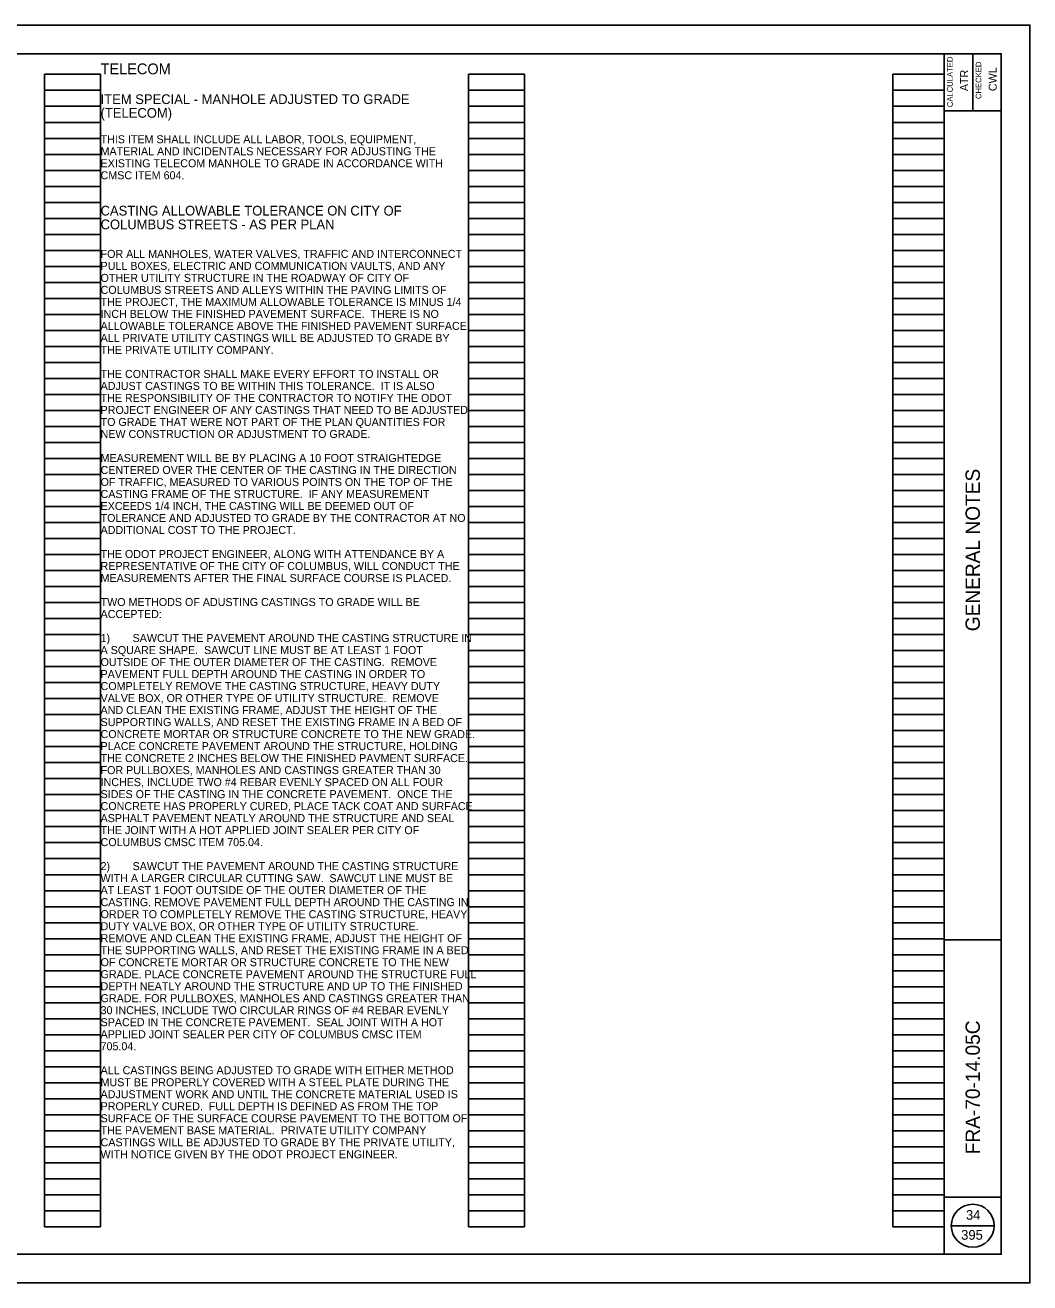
# Model space of a CAD drawing. Extents: x 0 to 34, y 0 to 22.
# Drawn here: x 16.42 to 34, y 0 to 22 of the extents above; entities that cross this region are included whole.
import ezdxf

# ---------------------------------------------------------------- set-up
doc = ezdxf.new("R2010")
doc.units = 0
for name, color, linetype in [('SC_Scratch1', 7, 'Continuous'), ('SH_Border', 7, 'Continuous'), ('SH_Cut_Line', 7, 'Continuous'), ('SH_Data', 7, 'Continuous'), ('SH_Text', 7, 'Continuous'), ('TX_P_1', 7, 'Continuous'), ('TX_P_Misc', 7, 'Continuous')]:
    doc.layers.add(name, color=color, linetype=linetype)

msp = doc.modelspace()

# ---------------------------------------------------------------- linework, layer by layer
at = {"layer": 'SC_Scratch1'}
for p, q in [((16.76, 0.98), (16.76, 21.14)), ((16.76, 21.14), (17.74, 21.14)), ((17.74, 0.98), (17.74, 21.14)), ((24.18, 0.98), (24.18, 21.14)), ((24.18, 21.14), (25.16, 21.14)), ((25.16, 0.98), (25.16, 21.14)), ((31.6, 0.98), (31.6, 21.14)), ((31.6, 21.14), (32.5, 21.14)), ((32.5, 0.98), (32.5, 21.14)), ((16.76, 20.86), (17.74, 20.86)), ((24.18, 20.86), (25.16, 20.86)), ((31.6, 20.86), (32.5, 20.86)), ((16.76, 20.58), (17.74, 20.58)), ((24.18, 20.58), (25.16, 20.58)), ((31.6, 20.58), (32.5, 20.58)), ((16.76, 20.3), (17.74, 20.3)), ((24.18, 20.3), (25.16, 20.3)), ((31.6, 20.3), (32.5, 20.3)), ((16.76, 20.02), (17.74, 20.02)), ((24.18, 20.02), (25.16, 20.02)), ((31.6, 20.02), (32.5, 20.02)), ((16.76, 19.74), (17.74, 19.74)), ((24.18, 19.74), (25.16, 19.74)), ((31.6, 19.74), (32.5, 19.74)), ((16.76, 19.46), (17.74, 19.46)), ((24.18, 19.46), (25.16, 19.46)), ((31.6, 19.46), (32.5, 19.46)), ((16.76, 19.18), (17.74, 19.18)), ((24.18, 19.18), (25.16, 19.18)), ((31.6, 19.18), (32.5, 19.18)), ((16.76, 18.9), (17.74, 18.9)), ((24.18, 18.9), (25.16, 18.9)), ((31.6, 18.9), (32.5, 18.9)), ((16.76, 18.62), (17.74, 18.62)), ((24.18, 18.62), (25.16, 18.62)), ((31.6, 18.62), (32.5, 18.62)), ((16.76, 18.34), (17.74, 18.34)), ((24.18, 18.34), (25.16, 18.34)), ((31.6, 18.34), (32.5, 18.34)), ((16.76, 18.06), (17.74, 18.06)), ((24.18, 18.06), (25.16, 18.06)), ((31.6, 18.06), (32.5, 18.06)), ((16.76, 17.78), (17.74, 17.78)), ((24.18, 17.78), (25.16, 17.78)), ((31.6, 17.78), (32.5, 17.78)), ((16.76, 17.5), (17.74, 17.5)), ((24.18, 17.5), (25.16, 17.5)), ((31.6, 17.5), (32.5, 17.5)), ((16.76, 17.22), (17.74, 17.22)), ((24.18, 17.22), (25.16, 17.22)), ((31.6, 17.22), (32.5, 17.22)), ((16.76, 16.94), (17.74, 16.94)), ((24.18, 16.94), (25.16, 16.94)), ((31.6, 16.94), (32.5, 16.94)), ((16.76, 16.66), (17.74, 16.66)), ((24.18, 16.66), (25.16, 16.66)), ((31.6, 16.66), (32.5, 16.66)), ((16.76, 16.38), (17.74, 16.38)), ((24.18, 16.38), (25.16, 16.38)), ((31.6, 16.38), (32.5, 16.38)), ((16.76, 16.1), (17.74, 16.1)), ((24.18, 16.1), (25.16, 16.1)), ((31.6, 16.1), (32.5, 16.1)), ((16.76, 15.82), (17.74, 15.82)), ((24.18, 15.82), (25.16, 15.82)), ((31.6, 15.82), (32.5, 15.82)), ((16.76, 15.54), (17.74, 15.54)), ((24.18, 15.54), (25.16, 15.54)), ((31.6, 15.54), (32.5, 15.54)), ((16.76, 15.26), (17.74, 15.26)), ((24.18, 15.26), (25.16, 15.26)), ((31.6, 15.26), (32.5, 15.26)), ((16.76, 14.98), (17.74, 14.98)), ((24.18, 14.98), (25.16, 14.98)), ((31.6, 14.98), (32.5, 14.98)), ((16.76, 14.7), (17.74, 14.7)), ((24.18, 14.7), (25.16, 14.7)), ((31.6, 14.7), (32.5, 14.7)), ((16.76, 14.42), (17.74, 14.42)), ((24.18, 14.42), (25.16, 14.42)), ((31.6, 14.42), (32.5, 14.42)), ((16.76, 14.14), (17.74, 14.14)), ((24.18, 14.14), (25.16, 14.14)), ((31.6, 14.14), (32.5, 14.14)), ((16.76, 13.86), (17.74, 13.86)), ((24.18, 13.86), (25.16, 13.86)), ((31.6, 13.86), (32.5, 13.86)), ((16.76, 13.58), (17.74, 13.58)), ((24.18, 13.58), (25.16, 13.58)), ((31.6, 13.58), (32.5, 13.58)), ((16.76, 13.3), (17.74, 13.3)), ((24.18, 13.3), (25.16, 13.3)), ((31.6, 13.3), (32.5, 13.3)), ((16.76, 13.02), (17.74, 13.02)), ((24.18, 13.02), (25.16, 13.02)), ((31.6, 13.02), (32.5, 13.02)), ((16.76, 12.74), (17.74, 12.74)), ((24.18, 12.74), (25.16, 12.74)), ((31.6, 12.74), (32.5, 12.74)), ((16.76, 12.46), (17.74, 12.46)), ((24.18, 12.46), (25.16, 12.46)), ((31.6, 12.46), (32.5, 12.46)), ((16.76, 12.18), (17.74, 12.18)), ((24.18, 12.18), (25.16, 12.18)), ((31.6, 12.18), (32.5, 12.18)), ((16.76, 11.9), (17.74, 11.9)), ((24.18, 11.9), (25.16, 11.9)), ((31.6, 11.9), (32.5, 11.9)), ((16.76, 11.62), (17.74, 11.62)), ((24.18, 11.62), (25.16, 11.62)), ((31.6, 11.62), (32.5, 11.62)), ((16.76, 11.34), (17.74, 11.34)), ((24.18, 11.34), (25.16, 11.34)), ((31.6, 11.34), (32.5, 11.34)), ((16.76, 11.06), (17.74, 11.06)), ((24.18, 11.06), (25.16, 11.06)), ((31.6, 11.06), (32.5, 11.06)), ((16.76, 10.78), (17.74, 10.78)), ((24.18, 10.78), (25.16, 10.78)), ((31.6, 10.78), (32.5, 10.78)), ((16.76, 10.5), (17.74, 10.5)), ((24.18, 10.5), (25.16, 10.5)), ((31.6, 10.5), (32.5, 10.5)), ((16.76, 10.22), (17.74, 10.22)), ((24.18, 10.22), (25.16, 10.22)), ((31.6, 10.22), (32.5, 10.22)), ((16.76, 9.94), (17.74, 9.94)), ((24.18, 9.94), (25.16, 9.94)), ((31.6, 9.94), (32.5, 9.94)), ((16.76, 9.66), (17.74, 9.66)), ((24.18, 9.66), (25.16, 9.66)), ((31.6, 9.66), (32.5, 9.66)), ((16.76, 9.38), (17.74, 9.38)), ((24.18, 9.38), (25.16, 9.38)), ((31.6, 9.38), (32.5, 9.38)), ((16.76, 9.1), (17.74, 9.1)), ((24.18, 9.1), (25.16, 9.1)), ((31.6, 9.1), (32.5, 9.1)), ((16.76, 8.82), (17.74, 8.82)), ((24.18, 8.82), (25.16, 8.82)), ((31.6, 8.82), (32.5, 8.82)), ((16.76, 8.54), (17.74, 8.54)), ((24.18, 8.54), (25.16, 8.54)), ((31.6, 8.54), (32.5, 8.54)), ((16.76, 8.26), (17.74, 8.26)), ((24.18, 8.26), (25.16, 8.26)), ((31.6, 8.26), (32.5, 8.26)), ((16.76, 7.98), (17.74, 7.98)), ((24.18, 7.98), (25.16, 7.98)), ((31.6, 7.98), (32.5, 7.98)), ((16.76, 7.7), (17.74, 7.7)), ((24.18, 7.7), (25.16, 7.7)), ((31.6, 7.7), (32.5, 7.7)), ((16.76, 7.42), (17.74, 7.42)), ((24.18, 7.42), (25.16, 7.42)), ((31.6, 7.42), (32.5, 7.42)), ((16.76, 7.14), (17.74, 7.14)), ((24.18, 7.14), (25.16, 7.14)), ((31.6, 7.14), (32.5, 7.14)), ((16.76, 6.86), (17.74, 6.86)), ((24.18, 6.86), (25.16, 6.86)), ((31.6, 6.86), (32.5, 6.86)), ((16.76, 6.58), (17.74, 6.58)), ((24.18, 6.58), (25.16, 6.58)), ((31.6, 6.58), (32.5, 6.58)), ((16.76, 6.3), (17.74, 6.3)), ((24.18, 6.3), (25.16, 6.3)), ((31.6, 6.3), (32.5, 6.3)), ((16.76, 6.02), (17.74, 6.02)), ((24.18, 6.02), (25.16, 6.02)), ((31.6, 6.02), (32.5, 6.02)), ((16.76, 5.74), (17.74, 5.74)), ((24.18, 5.74), (25.16, 5.74)), ((31.6, 5.74), (32.5, 5.74)), ((16.76, 5.46), (17.74, 5.46)), ((24.18, 5.46), (25.16, 5.46)), ((31.6, 5.46), (32.5, 5.46)), ((16.76, 5.18), (17.74, 5.18)), ((24.18, 5.18), (25.16, 5.18)), ((31.6, 5.18), (32.5, 5.18)), ((16.76, 4.9), (17.74, 4.9)), ((24.18, 4.9), (25.16, 4.9)), ((31.6, 4.9), (32.5, 4.9)), ((16.76, 4.62), (17.74, 4.62)), ((24.18, 4.62), (25.16, 4.62)), ((31.6, 4.62), (32.5, 4.62)), ((16.76, 4.34), (17.74, 4.34)), ((24.18, 4.34), (25.16, 4.34)), ((31.6, 4.34), (32.5, 4.34)), ((16.76, 4.06), (17.74, 4.06)), ((24.18, 4.06), (25.16, 4.06)), ((31.6, 4.06), (32.5, 4.06)), ((16.76, 3.78), (17.74, 3.78)), ((24.18, 3.78), (25.16, 3.78)), ((31.6, 3.78), (32.5, 3.78)), ((16.76, 3.5), (17.74, 3.5)), ((24.18, 3.5), (25.16, 3.5)), ((31.6, 3.5), (32.5, 3.5)), ((16.76, 3.22), (17.74, 3.22)), ((24.18, 3.22), (25.16, 3.22)), ((31.6, 3.22), (32.5, 3.22)), ((16.76, 2.94), (17.74, 2.94)), ((24.18, 2.94), (25.16, 2.94)), ((31.6, 2.94), (32.5, 2.94)), ((16.76, 2.66), (17.74, 2.66)), ((24.18, 2.66), (25.16, 2.66)), ((31.6, 2.66), (32.5, 2.66)), ((16.76, 2.38), (17.74, 2.38)), ((24.18, 2.38), (25.16, 2.38)), ((31.6, 2.38), (32.5, 2.38)), ((16.76, 2.1), (17.74, 2.1)), ((24.18, 2.1), (25.16, 2.1)), ((31.6, 2.1), (32.5, 2.1)), ((16.76, 1.82), (17.74, 1.82)), ((24.18, 1.82), (25.16, 1.82)), ((31.6, 1.82), (32.5, 1.82)), ((16.76, 1.54), (17.74, 1.54)), ((24.18, 1.54), (25.16, 1.54)), ((31.6, 1.54), (32.5, 1.54)), ((16.76, 1.26), (17.74, 1.26)), ((24.18, 1.26), (25.16, 1.26)), ((31.6, 1.26), (32.5, 1.26)), ((16.76, 0.98), (17.74, 0.98)), ((24.18, 0.98), (25.16, 0.98)), ((31.6, 0.98), (32.5, 0.98))]:
    msp.add_line(p, q, dxfattribs=at)
at = {"layer": 'SH_Border'}
for p, q in [((32.5, 0.5), (32.5, 21.5)), ((33, 21.5), (33, 20.5)), ((32.5, 20.5), (33.5, 20.5)), ((32.5, 6), (33.5, 6)), ((32.5, 1.5), (33.5, 1.5))]:
    msp.add_line(p, q, dxfattribs=at)
msp.add_lwpolyline([(2, 21.5), (33.5, 21.5), (33.5, 0.5), (2, 0.5)], close=True, dxfattribs=at)
at = {"layer": 'SH_Cut_Line'}
msp.add_lwpolyline([(0, 0), (34, 0), (34, 22), (0, 22)], close=True, dxfattribs=at)
at = {"layer": 'SH_Data'}
msp.add_line((32.625, 1), (33.375, 1), dxfattribs=at)
msp.add_circle((33, 1), 0.375, dxfattribs=at)

# ---------------------------------------------------------------- texts
for s, height, p in [('CALCULATED', 0.1, (32.652, 20.565)), ('CHECKED', 0.1, (33.152, 20.708)), ('ATR', 0.14, (32.92, 20.846)), ('CWL', 0.14, (33.42, 20.846)), ('GENERAL NOTES', 0.25, (33.125, 11.398)), ('FRA-70-14.05C', 0.25, (33.125, 2.249))]:
    msp.add_text(s, height=height, rotation=90, dxfattribs=at).set_placement(p)
for s, p in [('34', (32.882, 1.104)), ('395', (32.798, 0.754))]:
    msp.add_text(s, height=0.17, dxfattribs=at).set_placement(p)
at = {"layer": 'SH_Text'}
for s, p in [('THIS ITEM SHALL INCLUDE ALL LABOR, TOOLS, EQUIPMENT, ', (17.74, 19.934)), ('MATERIAL AND INCIDENTALS NECESSARY FOR ADJUSTING THE ', (17.74, 19.724)), ('EXISTING TELECOM MANHOLE TO GRADE IN ACCORDANCE WITH ', (17.74, 19.514)), ('CMSC ITEM 604.', (17.74, 19.304)), ('FOR ALL MANHOLES, WATER VALVES, TRAFFIC AND INTERCONNECT ', (17.74, 17.929)), ('PULL BOXES, ELECTRIC AND COMMUNICATION VAULTS, AND ANY ', (17.74, 17.719)), ('OTHER UTILITY STRUCTURE IN THE ROADWAY OF CITY OF ', (17.74, 17.509)), ('COLUMBUS STREETS AND ALLEYS WITHIN THE PAVING LIMITS OF ', (17.74, 17.299)), ('THE PROJECT, THE MAXIMUM ALLOWABLE TOLERANCE IS MINUS 1/4 ', (17.74, 17.089)), ('INCH BELOW THE FINISHED PAVEMENT SURFACE.  THERE IS NO ', (17.74, 16.879)), ('ALLOWABLE TOLERANCE ABOVE THE FINISHED PAVEMENT SURFACE. ', (17.74, 16.669)), ('ALL PRIVATE UTILITY CASTINGS WILL BE ADJUSTED TO GRADE BY ', (17.74, 16.459)), ('THE PRIVATE UTILITY COMPANY.', (17.74, 16.249)), ('THE CONTRACTOR SHALL MAKE EVERY EFFORT TO INSTALL OR ', (17.74, 15.829)), ('ADJUST CASTINGS TO BE WITHIN THIS TOLERANCE.  IT IS ALSO ', (17.74, 15.619)), ('THE RESPONSIBILITY OF THE CONTRACTOR TO NOTIFY THE ODOT ', (17.74, 15.409)), ('PROJECT ENGINEER OF ANY CASTINGS THAT NEED TO BE ADJUSTED ', (17.74, 15.199)), ('TO GRADE THAT WERE NOT PART OF THE PLAN QUANTITIES FOR ', (17.74, 14.989)), ('NEW CONSTRUCTION OR ADJUSTMENT TO GRADE.', (17.74, 14.779)), ('MEASUREMENT WILL BE BY PLACING A 10 FOOT STRAIGHTEDGE ', (17.74, 14.359)), ('OF TRAFFIC, MEASURED TO VARIOUS POINTS ON THE TOP OF THE ', (17.74, 13.939)), ('CENTERED OVER THE CENTER OF THE CASTING IN THE DIRECTION ', (17.74, 14.149)), ('CASTING FRAME OF THE STRUCTURE.  IF ANY MEASUREMENT ', (17.74, 13.729)), ('EXCEEDS 1/4 INCH, THE CASTING WILL BE DEEMED OUT OF ', (17.74, 13.519)), ('TOLERANCE AND ADJUSTED TO GRADE BY THE CONTRACTOR AT NO ', (17.74, 13.309)), ('ADDITIONAL COST TO THE PROJECT.', (17.74, 13.099)), ('THE ODOT PROJECT ENGINEER, ALONG WITH ATTENDANCE BY A ', (17.74, 12.679)), ('REPRESENTATIVE OF THE CITY OF COLUMBUS, WILL CONDUCT THE ', (17.74, 12.469)), ('MEASUREMENTS AFTER THE FINAL SURFACE COURSE IS PLACED. ', (17.74, 12.259)), ('TWO METHODS OF ADUSTING CASTINGS TO GRADE WILL BE ', (17.74, 11.839)), ('ACCEPTED:', (17.74, 11.629)), ('1)', (17.74, 11.209)), ('SAWCUT THE PAVEMENT AROUND THE CASTING STRUCTURE IN ', (18.3, 11.209)), ('A SQUARE SHAPE.  SAWCUT LINE MUST BE AT LEAST 1 FOOT ', (17.74, 10.999)), ('OUTSIDE OF THE OUTER DIAMETER OF THE CASTING.  REMOVE ', (17.74, 10.789)), ('PAVEMENT FULL DEPTH AROUND THE CASTING IN ORDER TO ', (17.74, 10.579)), ('COMPLETELY REMOVE THE CASTING STRUCTURE, HEAVY DUTY ', (17.74, 10.369)), ('VALVE BOX, OR OTHER TYPE OF UTILITY STRUCTURE.  REMOVE ', (17.74, 10.159)), ('AND CLEAN THE EXISTING FRAME, ADJUST THE HEIGHT OF THE ', (17.74, 9.949)), ('SUPPORTING WALLS, AND RESET THE EXISTING FRAME IN A BED OF ', (17.74, 9.739)), ('CONCRETE MORTAR OR STRUCTURE CONCRETE TO THE NEW GRADE. ', (17.74, 9.529)), ('PLACE CONCRETE PAVEMENT AROUND THE STRUCTURE, HOLDING ', (17.74, 9.319)), ('THE CONCRETE 2 INCHES BELOW THE FINISHED PAVMENT SURFACE.  ', (17.74, 9.109)), ('FOR PULLBOXES, MANHOLES AND CASTINGS GREATER THAN 30 ', (17.74, 8.899)), ('INCHES, INCLUDE TWO #4 REBAR EVENLY SPACED ON ALL FOUR ', (17.74, 8.689)), ('SIDES OF THE CASTING IN THE CONCRETE PAVEMENT.  ONCE THE ', (17.74, 8.479)), ('CONCRETE HAS PROPERLY CURED, PLACE TACK COAT AND SURFACE ', (17.74, 8.269)), ('ASPHALT PAVEMENT NEATLY AROUND THE STRUCTURE AND SEAL ', (17.74, 8.059)), ('THE JOINT WITH A HOT APPLIED JOINT SEALER PER CITY OF ', (17.74, 7.849)), ('COLUMBUS CMSC ITEM 705.04.', (17.74, 7.639)), ('2)', (17.74, 7.219)), ('SAWCUT THE PAVEMENT AROUND THE CASTING STRUCTURE ', (18.3, 7.219)), ('WITH A LARGER CIRCULAR CUTTING SAW.  SAWCUT LINE MUST BE ', (17.74, 7.009)), ('AT LEAST 1 FOOT OUTSIDE OF THE OUTER DIAMETER OF THE ', (17.74, 6.799)), ('CASTING. REMOVE PAVEMENT FULL DEPTH AROUND THE CASTING IN ', (17.74, 6.589)), ('ORDER TO COMPLETELY REMOVE THE CASTING STRUCTURE, HEAVY ', (17.74, 6.379)), ('DUTY VALVE BOX, OR OTHER TYPE OF UTILITY STRUCTURE.  ', (17.74, 6.169)), ('REMOVE AND CLEAN THE EXISTING FRAME, ADJUST THE HEIGHT OF ', (17.74, 5.959)), ('THE SUPPORTING WALLS, AND RESET THE EXISTING FRAME IN A BED ', (17.74, 5.749)), ('OF CONCRETE MORTAR OR STRUCTURE CONCRETE TO THE NEW ', (17.74, 5.539)), ('GRADE. PLACE CONCRETE PAVEMENT AROUND THE STRUCTURE FULL ', (17.74, 5.329)), ('DEPTH NEATLY AROUND THE STRUCTURE AND UP TO THE FINISHED ', (17.74, 5.119)), ('30 INCHES, INCLUDE TWO CIRCULAR RINGS OF #4 REBAR EVENLY ', (17.74, 4.699)), ('GRADE. FOR PULLBOXES, MANHOLES AND CASTINGS GREATER THAN ', (17.74, 4.909)), ('SPACED IN THE CONCRETE PAVEMENT.  SEAL JOINT WITH A HOT ', (17.74, 4.489)), ('APPLIED JOINT SEALER PER CITY OF COLUMBUS CMSC ITEM ', (17.74, 4.279)), ('705.04.', (17.74, 4.069)), ('ALL CASTINGS BEING ADJUSTED TO GRADE WITH EITHER METHOD ', (17.74, 3.649)), ('MUST BE PROPERLY COVERED WITH A STEEL PLATE DURING THE ', (17.74, 3.439)), ('ADJUSTMENT WORK AND UNTIL THE CONCRETE MATERIAL USED IS ', (17.74, 3.229)), ('PROPERLY CURED.  FULL DEPTH IS DEFINED AS FROM THE TOP ', (17.74, 3.019)), ('SURFACE OF THE SURFACE COURSE PAVEMENT TO THE BOTTOM OF ', (17.74, 2.809)), ('THE PAVEMENT BASE MATERIAL.  PRIVATE UTILITY COMPANY ', (17.74, 2.599)), ('CASTINGS WILL BE ADJUSTED TO GRADE BY THE PRIVATE UTILITY, ', (17.74, 2.389)), ('WITH NOTICE GIVEN BY THE ODOT PROJECT ENGINEER.', (17.74, 2.179))]:
    msp.add_text(s, height=0.14, dxfattribs=at).set_placement(p)
at = {"layer": 'TX_P_1'}
for s, height, p in [('TELECOM', 0.19, (17.74, 21.14)), ('ITEM SPECIAL - MANHOLE ADJUSTED TO GRADE ', 0.17, (17.74, 20.62)), ('(TELECOM)', 0.17, (17.74, 20.38))]:
    msp.add_text(s, height=height, dxfattribs=at).set_placement(p)
at = {"layer": 'TX_P_Misc'}
for s, p in [('CASTING ALLOWABLE TOLERANCE ON CITY OF ', (17.74, 18.67)), ('COLUMBUS STREETS - AS PER PLAN', (17.74, 18.43))]:
    msp.add_text(s, height=0.17, dxfattribs=at).set_placement(p)

doc.saveas('drawing.dxf')
